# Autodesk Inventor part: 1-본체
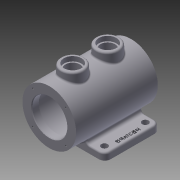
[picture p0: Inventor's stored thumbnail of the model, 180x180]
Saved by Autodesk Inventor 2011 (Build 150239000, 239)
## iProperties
Created: 2014-12
Part Number: 1-본체
Document SubType Name: Modeling
Designer: user
Density: 2.71 g/cm^3
Material: 알루미늄-6061
Mass: 1310.14 g
Surface Area: 1060.2 cm^2
Volume: 483.445 cm^3
Author: user
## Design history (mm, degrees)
sketch "스케치1"
  geometry: L1 (-47.5, 65)-(47.5, 65); L2 (47.5, 65)-(47.5, -65); L3 (47.5, -65)-(-47.5, -65); L4 (-47.5, -65)-(-47.5, 65); 3 further points
  constraints: 8 end point, 2 midpoint, 2 parallel, 1 horizontal, 1 horizontal alignment, 1 perpendicular, 1 vertical alignment
  dimensions: "d0" = 130 distance of L1.end L2.end; "d1" = 95 distance of L2.end L3.end
extrude "돌출1" new body sketch "스케치1" distance "d2" = 12; taper "d3" = 0 deg
sketch "스케치2"
  geometry: L1 (77.5, 50)-(-62.5, 50); L2 (-47.5, 0)-(-47.5, 12) reference; L3 (47.5, 0)-(-47.5, 0) reference; L4 (77.5, 80)-(77.5, 96); L5 (77.5, 96)-(-62.5, 96); L6 (-62.5, 96)-(-62.5, 80); L7 (-62.5, 80)-(-50.5, 80); L8 (-50.5, 80)-(-50.5, 87.5); L9 (-50.5, 87.5)-(65.5, 87.5); L10 (65.5, 87.5)-(65.5, 80); L11 (65.5, 80)-(77.5, 80); 5 further points
  constraints: 18 end point, 6 parallel, 4 midpoint, 2 perpendicular, 2 vertical alignment, 1 collinear, 1 horizontal, 1 horizontal alignment
  dimensions: "d4" = 140 distance of L1.start L1.end; "d5" = 15 distance from line of L2 L1.end; "d6" = 50 distance between parallel lines of L3 L1; "d7" = 12 distance of L10.end L4.start; "d8" = 60 diameter of point (71.5, 80) L1; "d9" = 75 diameter of L9 L1; "d10" = 92 diameter of L5 L1
revolve "회전1" sketch "스케치2" stored, may be unused: angle "d11" = 90 deg
node "작업 평면2"
  node "작업 평면1"
sketch "스케치3"
  geometry: L1 (70, 46)-(70, -46) reference; L2 (-70, 46)-(-70, -46) reference; L3 (-40, -25.923)-(-40, 25.923) reference; L4 (55, -25.923)-(-40, -25.923) reference; L5 (55, 25.923)-(55, -25.923) reference; L6 (-40, 25.923)-(55, 25.923) reference; C1 r 20 at (-30, 0); C2 r 20 at (30, 0); 1 further point
  constraints: 2 centre point, 2 horizontal alignment
  dimensions: "d13" = 40 diameter of C1; "d14" = 40 diameter of C2; "d15" = 40 distance from line of L2 C1.centre; "d16" = 60 distance of C1.centre C2.centre
extrude "돌출2" join sketch "스케치3" stored distance "d17" = 12; taper "d18" = 0 deg
sketch "스케치4"
  geometry: C1 r 20 at (0, 0) reference; C2 r 20 at (60, 0) reference; 1 further point
hole "Hole1" sketch "스케치4" at (0, 0), (60, 0) diameter "d19" = 25; stored, may be unused: countersink angle "d23" = 90 deg, drill point angle "d25" = 118 deg; dims "d20" = 6, "d21" = 30, "d22" = 8, "d24" = 8
chamfer "모따기1" distance "d26" = 1; stored, may be unused: second distance "d27" = 2, angle "d28" = 45 deg
fillet "모깎기1" dims "d29" = 3
fillet "모깎기2" dims "d30" = 5
sketch "스케치5"
  geometry: L1 (0, 0)-(40, 0); L2 (0, 0)-(28.284, -28.284); C1 r 31 at (0, 0) reference; 2 further points
  constraints: 4 end point, 1 coincident, 1 horizontal
  dimensions: "d32" = 40 distance of L1.start L1.end; "d33" = 40 distance of L1.start L2.end; "d34" = 45 deg angle of L2 L1
hole "Hole2" sketch "스케치5" at (28.284, -28.284) diameter "d35" = 3.242; stored, may be unused: countersink angle "d39" = 90 deg, drill point angle "d41" = 118 deg; dims "d36" = 8, "d37" = 4, "d38" = 2, "d40" = 10
sketch "스케치6"
  geometry: L1 (0, 0)-(-40, 0); L2 (0, 0)-(-28.284, 28.284); C1 r 31 at (0, 0) reference; 2 further points
  constraints: 4 end point, 1 coincident, 1 horizontal
  dimensions: "d45" = 40 distance of L1.start L1.end; "d46" = 40 distance of L1.start L2.end; "d47" = 45 deg angle of L2 L1
hole "Hole3" sketch "스케치6" at (-28.284, 28.284) diameter "d48" = 3.242; stored, may be unused: countersink angle "d52" = 90 deg, drill point angle "d54" = 118 deg; dims "d49" = 8, "d50" = 4, "d51" = 2, "d53" = 10
fillet "모깎기3" dims "d58" = 10
fillet "모깎기4" dims "d59" = 3
sketch "스케치7"
  geometry: L1 (44.5, -38.884)-(44.5, -55) reference; L2 (-44.5, -38.884)-(44.5, -38.884) reference; L3 (-44.5, -55)-(-44.5, -38.884) reference; L4 (37.5, -62)-(-37.5, -62) reference; L5 (37.5, 65)-(-37.5, 65) reference; L6 (47.5, 38.884)-(47.5, 55) reference; C1 r 5.5 at (35, 52); C2 r 5.5 at (-35, 52); C3 r 5.5 at (35, -52); C4 r 5.5 at (-35, -52); A1 r 7 centre (-37.5, -55) between (-44.5, -55) and (-37.5, -62) reference; A2 r 7 centre (37.5, -55) between (37.5, -62) and (44.5, -55) reference; 1 further point
  constraints: 4 centre point, 2 horizontal alignment, 2 vertical alignment
  dimensions: "d60" = 11 diameter of C1; "d61" = 11 diameter of C2; "d62" = 11 diameter of C3; "d63" = 11 diameter of C4; "d66" = 12.5 distance from line of L6 C1.centre; "d67" = 104 distance of C3.centre C1.centre; "d69" = 70 distance of C2.centre C1.centre; "d70" = 13 vertical distance of L5.start C1.centre
hole "Hole4" sketch "스케치7" at (-35, -52), (35, -52), (-35, 52), (35, 52) diameter "d71" = 11; stored, may be unused: countersink angle "d75" = 90 deg, drill point angle "d77" = 118 deg; dims "d72" = 8, "d73" = 4, "d74" = 2, "d76" = 10
fillet "모깎기5" dims "d78" = 3
sketch "스케치8"
  geometry: L1 (-22.5, -54)-(22.5, -54); L2 (22.5, -54)-(22.5, -60); L3 (22.5, -60)-(-22.5, -60); L4 (-22.5, -60)-(-22.5, -54); L5 (-22.5, -57)-(22.5, -57); L6 (0, -54)-(0, -60); L7 (-37.5, -65)-(37.5, -65) reference; C1 r 5.5 at (-35, -52) reference; 1 further point
  constraints: 4 end point, 4 midpoint, 2 other
  dimensions: "d83" = 8 distance between parallel lines of L7 L5; "d84" = 35 distance from line of C1.centre L6; "d85" = 6 distance between parallel lines of L3 L1; "d86" = 45 distance between parallel lines of L2 L4
feature "엠보싱1" sketch "스케치8" dims "d0" = 130, "d1" = 95, "d10" = 92, "d87" = 1, "d88" = 0
fillet "모깎기6" dims "d89" = 3
fillet "모깎기7" dims "d90" = 3
node "솔리드1"
pattern_circular "원형 패턴1" dims angle "d43" = 360 deg
pattern_circular "원형 패턴2" dims angle "d56" = 360 deg
node "투영된 루프1"
node "투영된 루프2"
node "투영된 루프3"
